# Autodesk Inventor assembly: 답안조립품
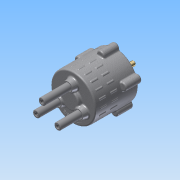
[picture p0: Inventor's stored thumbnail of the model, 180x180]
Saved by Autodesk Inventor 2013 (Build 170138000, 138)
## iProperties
Created: 2016-01
Part Number: 답안조립품
Document SubType Name: Assembly
Designer: Administrator
Mass: 2097.9 g
Surface Area: 1856.21 cm^2
Volume: 450.789 cm^3
Density: 4.65385 g/cm^3
Author: Administrator
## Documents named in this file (14)
- C:\Users\Administrator\Desktop\360106V1041\답안조립품.iam
- C:\Users\Administrator\Desktop\360106V1041\본체.ipt
- C:\Users\Administrator\Desktop\360106V1041\베어링 NA 4900.ipt
- C:\Users\Administrator\Desktop\360106V1041\슬라이드 축.ipt
- C:\Users\Administrator\Desktop\360106V1041\가변스프링-1.ipt
- C:\Users\Administrator\Desktop\360106V1041\가변스프링-2.ipt
- C:\Users\Administrator\Desktop\360106V1041\가변스프링-3.ipt
- C:\Users\Administrator\Desktop\360106V1041\메인 축.ipt
- C:\Users\Administrator\Desktop\360106V1041\멈춤링 10 x 1.ipt
- C:\Users\Administrator\Desktop\360106V1041\멈춤링 22 x 1.2.ipt
- C:\Users\Administrator\Desktop\360106V1041\판캠.ipt
- C:\Users\Administrator\Desktop\360106V1041\커버.ipt
- C:\Users\Administrator\Desktop\360106V1041\M5x0.8x20.ipt
- C:\Users\Administrator\Desktop\360106V1041\오일실.ipt
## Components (8 placed, 4 different names)
1. 가변스프링-1:1
2. 가변스프링-2:1
3. 가변스프링-3:1
4. M5x0.8x20:1
5. M5x0.8x20:2
6. M5x0.8x20:3
7. M5x0.8x20:4
8. M5x0.8x20:5
